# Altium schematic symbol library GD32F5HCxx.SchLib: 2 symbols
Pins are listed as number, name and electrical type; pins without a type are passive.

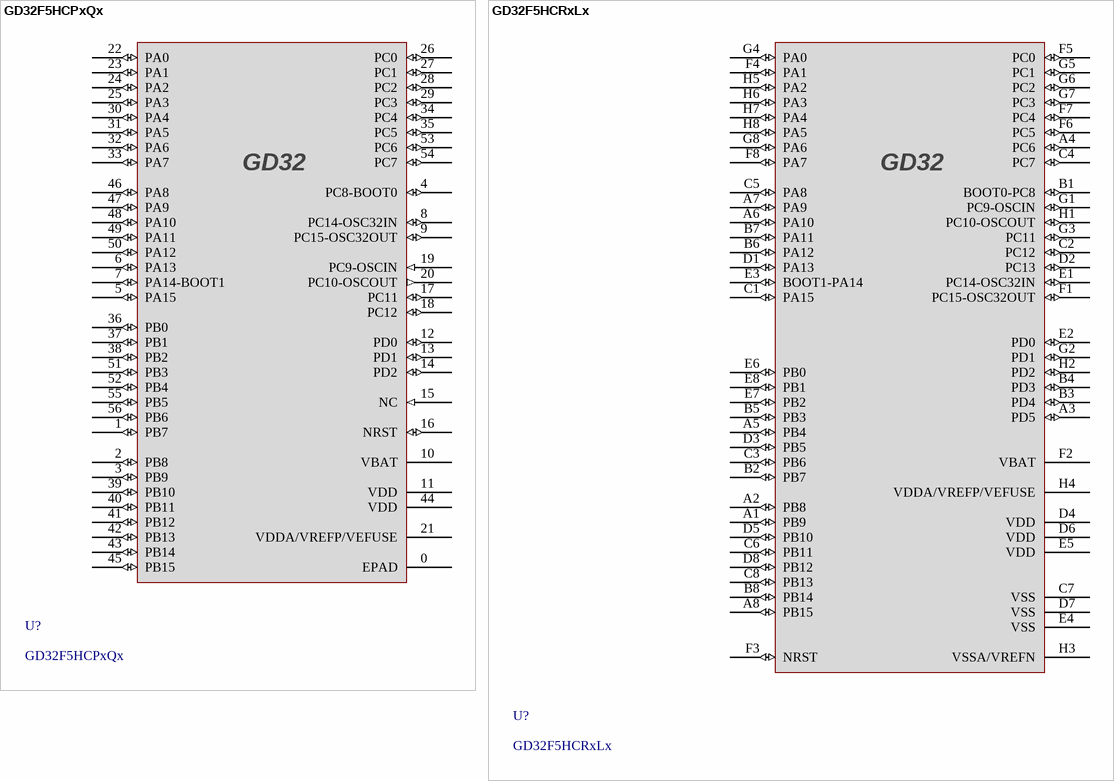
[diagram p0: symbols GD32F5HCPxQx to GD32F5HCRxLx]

## GD32F5HCPxQx
designator U?
footprint QFN56_7X7X0.8
pins: 0 EPAD (power), 1 PB7 (io), 2 PB8 (io), 3 PB9 (io), 4 PC8-BOOT0 (io), 5 PA15 (io), 6 PA13 (io), 7 PA14-BOOT1 (io), 8 PC14-OSC32IN (io), 9 PC15-OSC32OUT (io), 10 VBAT (power), 11 VDD (power), 12 PD0 (io), 13 PD1 (io), 14 PD2 (io), 15 NC (in), 16 NRST (io), 17 PC11 (io), 18 PC12 (io), 19 PC9-OSCIN (in), 20 PC10-OSCOUT (out), 21 VDDA/VREFP/VEFUSE (power), 22 PA0 (io), 23 PA1 (io), 24 PA2 (io), 25 PA3 (io), 26 PC0 (io), 27 PC1 (io), 28 PC2 (io), 29 PC3 (io), 30 PA4 (io), 31 PA5 (io), 32 PA6 (io), 33 PA7 (io), 34 PC4 (io), 35 PC5 (io), 36 PB0 (io), 37 PB1 (io), 38 PB2 (io), 39 PB10 (io), 40 PB11 (io), 41 PB12 (io), 42 PB13 (io), 43 PB14 (io), 44 VDD (power), 45 PB15 (io), 46 PA8 (io), 47 PA9 (io), 48 PA10 (io), 49 PA11 (io), 50 PA12 (io), 51 PB3 (io), 52 PB4 (io), 53 PC6 (io), 54 PC7 (io), 55 PB5 (io), 56 PB6 (io)

## GD32F5HCRxLx
designator U?
footprint BGA64_4x4X0.84
pins: A1 PB9 (io), A2 PB8 (io), A3 PD5 (io), A4 PC6 (io), A5 PB4 (io), A6 PA10 (io), A7 PA9 (io), A8 PB15 (io), B1 BOOT0-PC8 (io), B2 PB7 (io), B3 PD4 (io), B4 PD3 (io), B5 PB3 (io), B6 PA12 (io), B7 PA11 (io), B8 PB14 (io), C1 PA15 (io), C2 PC12 (io), C3 PB6 (io), C4 PC7 (io), C5 PA8 (io), C6 PB11 (io), C7 VSS, C8 PB13 (io), D1 PA13 (io), D2 PC13 (io), D3 PB5 (io), D4 VDD (power), D5 PB10 (io), D6 VDD (power), D7 VSS (power), D8 PB12 (io), E1 PC14-OSC32IN (io), E2 PD0 (io), E3 BOOT1-PA14 (io), E4 VSS, E5 VDD (power), E6 PB0 (io), E7 PB2 (io), E8 PB1 (io), F1 PC15-OSC32OUT (io), F2 VBAT (power), F3 NRST (io), F4 PA1 (io), F5 PC0 (io), F6 PC5 (io), F7 PC4 (io), F8 PA7 (io), G1 PC9-OSCIN (io), G2 PD1 (io), G3 PC11 (io), G4 PA0 (io), G5 PC1 (io), G6 PC2 (io), G7 PC3 (io), G8 PA6 (io), H1 PC10-OSCOUT (io), H2 PD2 (io), H3 VSSA/VREFN (power), H4 VDDA/VREFP/VEFUSE (power), H5 PA2 (io), H6 PA3 (io), H7 PA4 (io), H8 PA5 (io)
